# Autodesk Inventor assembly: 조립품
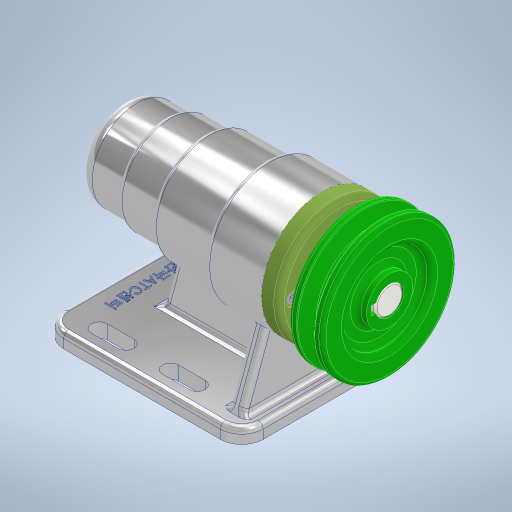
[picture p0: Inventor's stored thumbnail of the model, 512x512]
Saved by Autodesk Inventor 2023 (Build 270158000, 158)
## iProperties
Created: 2022-07
Part Number: 조립품
Document SubType Name: Assembly
Designer: owner
Author: owner
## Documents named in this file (12)
- C:\Users\owner\Desktop\720708V1005\조립품.iam
- C:\Users\owner\Desktop\720708V1005\본체.ipt
- C:\Users\owner\Desktop\720708V1005\V벨트풀리.ipt
- C:\Users\owner\Desktop\720708V1005\멈춤나사 M3.ipt
- C:\Users\owner\Desktop\720708V1005\베어링 6004.ipt
- C:\Users\owner\Desktop\720708V1005\베어링 51202.ipt
- C:\Users\owner\Desktop\720708V1005\볼트 M4.ipt
- C:\Users\owner\Desktop\720708V1005\어댑터슬리브.ipt
- C:\Users\owner\Desktop\720708V1005\오일 실 20x35x7.ipt
- C:\Users\owner\Desktop\720708V1005\축.ipt
- C:\Users\owner\Desktop\720708V1005\커버.ipt
- C:\Users\owner\Desktop\720708V1005\키 5x5.ipt
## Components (1 placed, 1 different names)
1. V벨트풀리:1
